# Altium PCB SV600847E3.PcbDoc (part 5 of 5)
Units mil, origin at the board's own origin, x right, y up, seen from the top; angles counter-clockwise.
Board outline 5404 x 2680 mil, 10 copper layers (Top Layer L1, Gnd-Plane - L2, Signals - L3, Gnd-Plane - L4, Pwr Plane - L5, Signals - L6, Gnd-Plane - L7, Signals - L8, Gnd-Plane - L9, Bottom Layer - L10), stack 57.8 mil thick; 517 components, 320 nets, 1784 pads, 1289 vias.
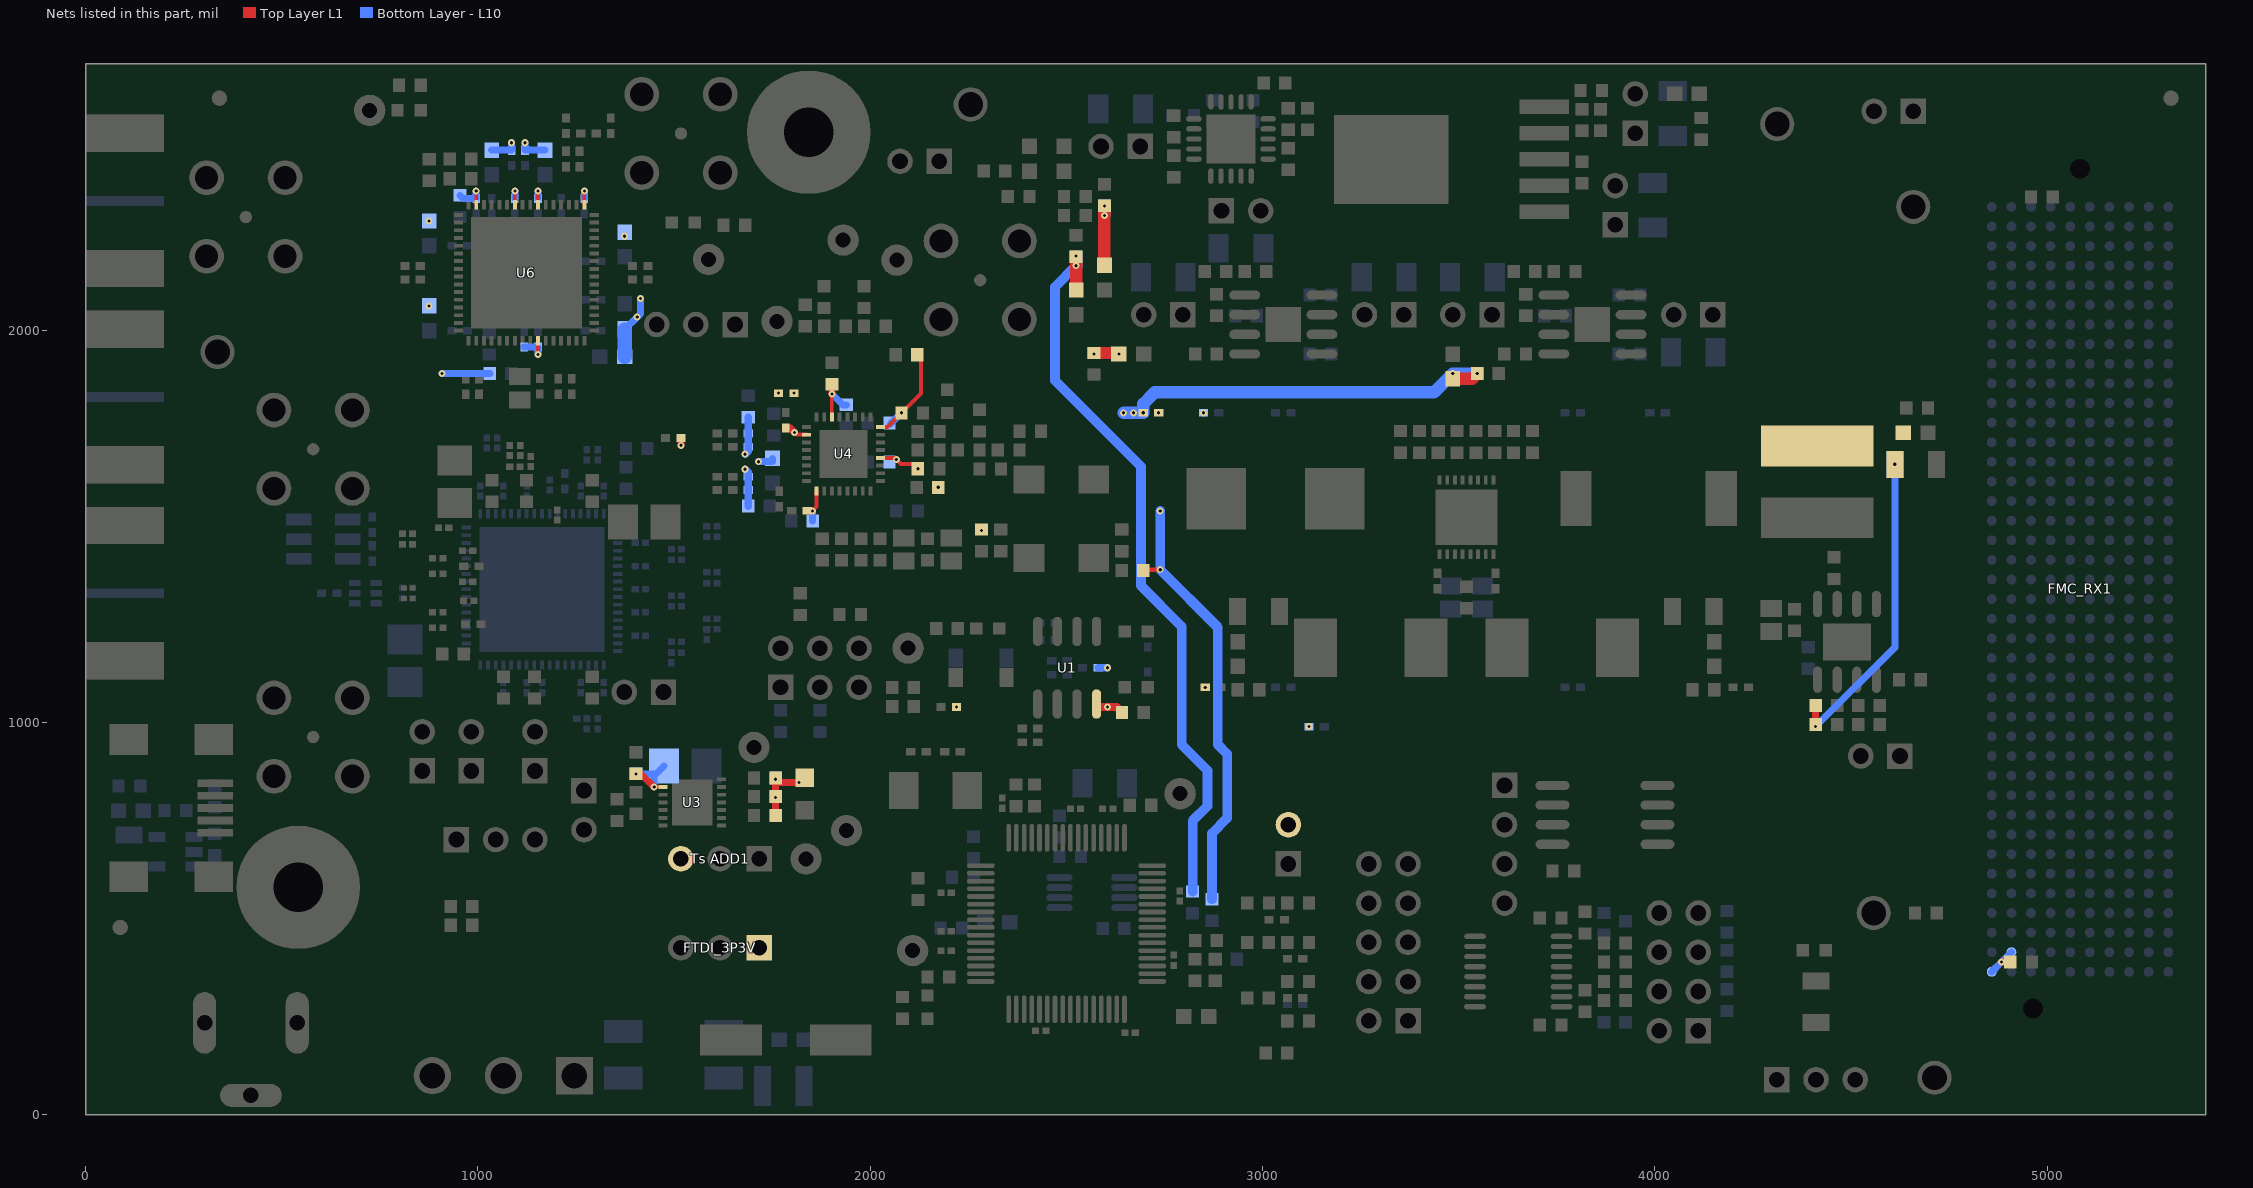
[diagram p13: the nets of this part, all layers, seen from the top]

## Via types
v1: diameter 18, hole 8, Top Layer L1 to Bottom Layer - L10, tented both sides, 1069 vias
v2: diameter 19.68, hole 7.87, Top Layer L1 to Bottom Layer - L10, 95 vias
v3: diameter 18, hole 8, Top Layer L1 to Bottom Layer - L10, tented bottom, 56 vias
v4: diameter 18, hole 8, Top Layer L1 to Bottom Layer - L10, tented top, 54 vias
v5: diameter 25.98, hole 12.99, Top Layer L1 to Bottom Layer - L10, tented top, 8 vias
v6: diameter 19.68, hole 7.87, Top Layer L1 to Bottom Layer - L10, tented top, 5 vias
v7: diameter 126, hole 106, Top Layer L1 to Bottom Layer - L10, tented top, 2 vias

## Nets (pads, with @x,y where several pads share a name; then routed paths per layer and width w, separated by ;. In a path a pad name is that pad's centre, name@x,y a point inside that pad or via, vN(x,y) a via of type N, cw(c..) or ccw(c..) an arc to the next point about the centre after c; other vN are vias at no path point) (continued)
VIO_3P3V: "Ts ADD1.3" C24.1 C25.1 C27.1 C115.1 C125.1 C153.1 C163.1 C215.1 C216.1 C217.1 C218.1 C219.2 C220.1 C224.2 FTDI_3P3V.1 J3.2 L9.2 R1.2 R14.2 R15.2 R16.2 R31.2 R32.2 TEMP.1 U1.8 U3.2 | length 670
  Top Layer L1 w9: v1(1449.28,836.13) U3.2@1471.47,836.13
  Top Layer L1 w18: v1(1403.28,869.44) 1415.96,869.44 v1(1449.28,836.13) ; v1(1517.68,1707.16) C215.1@1517.68,1726 ; R16.2@1758.84,763.41 v1(1758.84,809.41) 1758.84,847.47 v1(1818.28,847.47)
  Top Layer L1 w19.5: U1.8@2577,1040 2627.93,1040 C125.1@2641.93,1026
  Top Layer L1 w30: C153.1@2570,1942.56 2631.45,1942.56 v1(2634.01,1940)
  Bottom Layer - L10 w18: v1(1403.28,869.44) 1454.17,869.44 C27.1@1474.14,889.42 ; v1(1449.28,836.13) C27.1@1449.3,869.44 ; v1(1758.84,809.41) v1(1758.84,855.81) ; v1(2570,1940) v1(2634.01,1940) ; R1.2@2580.69,1140 v1(2604.5,1140)
  Bottom Layer - L10 w19.5: v1(2604.5,1040) 2627.93,1040 C115.1@2641.93,1026
  other v1: 3118.32,990 2219.68,1040 2854.16,1090 2735.24,1790 2849.31,1790 1766.32,1840
VIO_3P3V_LMK_CLK: C116.1 C171.1 L2.1 L4.1 L13.2 L19.1 L21.1 L22.1 R47.2 R131.1 | length 2191.3
  Top Layer L1 w31.5: L13.2@2525,2102.99 C116.1@2525,2187.44
  Bottom Layer - L10 w18: v1(908,1890) R47.2@1030.23,1890 ; L4.1@1373.92,2001.92 v1(1406,2034) 1414,2042 v1(1414,2081)
  Bottom Layer - L10 w25: v1(2525,2165) 2471,2111 2471,1872 2690,1653 2690,1349 2794,1245 2794,944 2860,878 2860,788 2822,750 R131.1@2822,569.71
  Bottom Layer - L10 w31.5: v1@2525,2162.44 C171.1@2525,2187.44
  Bottom Layer - L10 w37.5: L2.1@1373.92,1932.5 L4.1@1373.92,2001.92
  other v1: 875.5,2062.35 2525,2190 1373.92,2240 875.5,2278.89
VIO_3P3V_LMK_PLL: C102.1 C104.1 C107.1 C108.1 C109.1 C164.1 C165.1 C206.1 C207.1 C208.1 C209.1 L3.1 L5.1 L10.2 U6.10 U6.33 U6.39 U6.42 U6.47 | length 666.3
  Top Layer L1 w9: U6.47@995.61,2320.23 v1(995.61,2355.31) ; U6.42@1094.03,2320.23 v1(1094.03,2355.31) ; v1(1153.09,1938.69) U6.10@1153.09,1973.77 ; U6.39@1153.09,2320.23 v1(1153.09,2355.31) ; U6.33@1271.2,2320.23 v1(1271.2,2355.31)
  Top Layer L1 w31.5: L10.2@2597,2165.99 v1(2597,2317.5)
  Bottom Layer - L10 w18: C108.1@953.92,2344.32 961.79,2336.44 C209.1@995.61,2336.45 v1(995.61,2355.31) ; L5.1@1034.98,2459.5 C107.1@1085.92,2459.5 v1(1085.92,2478.37) ; C208.1@1094.03,2336.45 v1(1094.03,2355.31) ; C109.1@1117.72,1957.55 C102.1@1153.09,1957.55 v1(1153.09,1938.69) ; v1(1119.92,2478.37) C104.1@1119.92,2459.5 L3.1@1170.95,2459.5 ; C207.1@1153.09,2336.45 v1(1153.09,2355.31) ; C206.1@1271.2,2336.45 v1(1271.2,2355.31)
  Bottom Layer - L10 w31.5: v1(2597,2292.5) v1(2597,2317.5)
VIO_3P3V_LMX: C75.2 C76.2 C77.2 C78.2 C88.1 C89.1 C91.1 C94.1 C95.2 C98.2 C99.2 C144.1 C152.1 C216.2 C217.2 L1.1 L6.2 R24.1 R35.2 R36.1 R37.2 R38.1 R46.2 R117.2 R130.1 R133.2 U4.6 U4.10 U4.17 U4.28 U4.32 | length 3054.9
  Top Layer L1 w9: U4.6@1902.35,1779.45 v1(1902.35,1838)
  Top Layer L1 w10: v1(1806.92,1740) 1812.75,1734.17 U4.10@1837.39,1734.17 ; v1(1852.43,1540) 1862.98,1550.55 U4.17@1862.98,1590.47 ; U4.28@2026.36,1675.11 2062.5,1675.11 v1(2066.5,1671.11) 2078.62,1659 2109.99,1659 v1(2121.58,1647.41) ; U4.32@2026.36,1753.85 2043.85,1753.85 C77.2@2079.58,1789.58 2129,1839.01 2129,1928.87 R117.2@2119.87,1938
  Top Layer L1 w12.5: R133.2@2696.32,1390 v1(2739.2,1390)
  Top Layer L1 w18: C75.2@1839.62,1540 v1(1852.43,1540) ; v1(1902.35,1838) C89.1@1902.35,1862.75
  Top Layer L1 w19: C95.2@1784.89,1751.11 1795.81,1751.11 v1(1806.92,1740)
  Top Layer L1 w31.5: L6.2@3485,1876.5 3533.94,1876.5 v1(3547.44,1890)
  Bottom Layer - L10 w18: v1(1715,1665.27) 1751,1665.27 L1.1@1751,1674 ; C94.1@1852.43,1514.27 v1(1852.43,1540) ; v1(1902.35,1838) 1930.25,1810.1 C88.1@1938.95,1810.1 ; C78.2@2051.53,1761.95 v1(2079.58,1790)
  Bottom Layer - L10 w19: v1(1681,1646.11) 1688.96,1638.15 R36.1@1688.96,1593.27 C98.2@1688.96,1552.1 ; v1(1681,1684.43) 1688.96,1692.39 R37.2@1688.96,1737.27 C99.2@1688.96,1778.44
  Bottom Layer - L10 w25: v1(2739.2,1540) v1(2739.2,1390) 2886,1243.2 2886,944 2910,920 2910,757 2871,718 R130.1@2871,550.02
  Bottom Layer - L10 w31.5: v1(2645.87,1790) v1(2695.87,1790) 2695.87,1812.87 2725,1842 3437,1842 v1(3485,1890) v1(3547.44,1890)
  other v1: 2283.8,1490 2173.35,1600.02 2670.87,1790 1805.69,1840
VIO_3P6V: C154.2 C156.2 C157.2 L7.1 L8.2 R72.1 | length 801.4
  Top Layer L1 w18: R72.1@4409.88,995 C154.2@4409.88,1044
  Bottom Layer - L10 w18: v1(4409.88,990) 4611.85,1191.97 v1(4611.85,1658.75)
VIO_B_M2C_RX: FMC_RX1.J39 FMC_RX1.K40 RR7.2 | length 93.2
  Top Layer L1 w18: v1(4884,390) RR7.2@4906.44,390
  Bottom Layer - L10 w18: FMC_RX1.K40@4859,365 v1(4884,390) FMC_RX1.J39@4909,415
pads on no net: 5VDC.3 "SH-Ts ADD1_1_2.0" FID1.1 FID2.1 FID3.1 FMC_RX1.401 FMC_RX1.402 FMC_RX1.A22 FMC_RX1.A23 FMC_RX1.A26 FMC_RX1.A27 FMC_RX1.A30 FMC_RX1.A31 FMC_RX1.A34 FMC_RX1.A35 FMC_RX1.A38 FMC_RX1.A39 FMC_RX1.B1 FMC_RX1.B4 FMC_RX1.B5 FMC_RX1.B8 FMC_RX1.B9 FMC_RX1.B20 FMC_RX1.B21 FMC_RX1.B24 FMC_RX1.B25 FMC_RX1.B28 FMC_RX1.B29 FMC_RX1.B32 FMC_RX1.B33 FMC_RX1.B36 FMC_RX1.B37 FMC_RX1.B40 FMC_RX1.C2 FMC_RX1.C3 FMC_RX1.C10 FMC_RX1.C11 FMC_RX1.C14 FMC_RX1.C15 FMC_RX1.C18 FMC_RX1.C19 FMC_RX1.C22 FMC_RX1.C23 FMC_RX1.C26 FMC_RX1.C27 FMC_RX1.D8 FMC_RX1.D9 FMC_RX1.D11 FMC_RX1.D12 FMC_RX1.D14 FMC_RX1.D15 FMC_RX1.D17 FMC_RX1.D18 FMC_RX1.D20 FMC_RX1.D21 FMC_RX1.D23 FMC_RX1.D24 FMC_RX1.D27 FMC_RX1.D29 FMC_RX1.D33 FMC_RX1.D34 FMC_RX1.E2 FMC_RX1.E3 FMC_RX1.E6 FMC_RX1.E7 FMC_RX1.E9 FMC_RX1.E10 FMC_RX1.E15 FMC_RX1.E16 FMC_RX1.E18 FMC_RX1.E19 FMC_RX1.E21 FMC_RX1.E22 FMC_RX1.E24 FMC_RX1.E25 FMC_RX1.E27 FMC_RX1.E28 FMC_RX1.E30 FMC_RX1.E31 FMC_RX1.E33 FMC_RX1.E34 FMC_RX1.E37 FMC_RX1.F4 FMC_RX1.F5 FMC_RX1.F7 FMC_RX1.F8 FMC_RX1.F10 FMC_RX1.F11 FMC_RX1.F13 FMC_RX1.F14 FMC_RX1.F16 FMC_RX1.F17 FMC_RX1.F19 FMC_RX1.F20 FMC_RX1.F22 FMC_RX1.F23 FMC_RX1.F25 FMC_RX1.F26 FMC_RX1.F28 FMC_RX1.F29 FMC_RX1.F31 FMC_RX1.F32 FMC_RX1.F34 FMC_RX1.F35 FMC_RX1.F37 FMC_RX1.F38 FMC_RX1.G2 FMC_RX1.G3 FMC_RX1.G15 FMC_RX1.G16 FMC_RX1.G18 FMC_RX1.G19 FMC_RX1.G21 FMC_RX1.G22 FMC_RX1.G24 FMC_RX1.G25 FMC_RX1.G28 FMC_RX1.G31 FMC_RX1.H1 FMC_RX1.H4 FMC_RX1.H5 FMC_RX1.H7 FMC_RX1.H8 FMC_RX1.H10 FMC_RX1.H11 FMC_RX1.H13 FMC_RX1.H14 FMC_RX1.H16 FMC_RX1.H17 FMC_RX1.H19 FMC_RX1.H20 FMC_RX1.H25 FMC_RX1.H26 FMC_RX1.H28 FMC_RX1.H29 FMC_RX1.H32 FMC_RX1.H35 FMC_RX1.J2 FMC_RX1.J3 FMC_RX1.J6 FMC_RX1.J7 FMC_RX1.J9 FMC_RX1.J10 FMC_RX1.J12 FMC_RX1.J13 FMC_RX1.J18 FMC_RX1.J19 FMC_RX1.J21 FMC_RX1.J22 FMC_RX1.J24 FMC_RX1.J25 FMC_RX1.J27 FMC_RX1.J28 FMC_RX1.J30 FMC_RX1.J31 FMC_RX1.J33 FMC_RX1.J34 FMC_RX1.J36 FMC_RX1.J37 FMC_RX1.K1 FMC_RX1.K4 FMC_RX1.K5 FMC_RX1.K7 FMC_RX1.K8 FMC_RX1.K10 FMC_RX1.K11 FMC_RX1.K13 FMC_RX1.K14 FMC_RX1.K16 FMC_RX1.K17 FMC_RX1.K19 FMC_RX1.K20 FMC_RX1.K22 FMC_RX1.K23 FMC_RX1.K25 FMC_RX1.K26 FMC_RX1.K28 FMC_RX1.K29 FMC_RX1.K31 FMC_RX1.K32 FMC_RX1.K34 FMC_RX1.K35 FMC_RX1.K37 FMC_RX1.K38 H3.0 H4.0 H5.1 H6.1 S1.3 SH-1V2ADC_INT_1_2.0 SH-1V2ADC_LDO_1_2.0 SH-1V9ADC_1_2.0 SH-1V9INT_1_2.0 SH-5V_12V_1_2.0 SH-FTDI_3P3V_1_2.0 SH-LMK_INT_1_2.0 SH-LMK_LDO_1_2.0 SH-LMX_INT_1_2.0 SH-LMX_LDO_1_2.0 SH-RSV_1_2.0 U3.1 U3.3 U3.4 U5.2 U5.7 U8.2 U8.7 U10.2 U10.3 U10.4 U10.9 U10.13 U10.14 U10.17 U13.21 U13.22 U13.23 U13.24 U13.27 U13.29 U13.30 U13.32 U13.33 U13.34 U13.36 U13.45 U13.46 U13.48 U13.52 U13.53 U13.54 U13.55 U13.57 U13.58 U13.59 U13.60 U15.6 U15.7 U16.7 USB.4 uWIRE.1 uWIRE.3 uWIRE.5 uWIRE.7
copper on no net:
  other v7: 5005,100 5005,2580

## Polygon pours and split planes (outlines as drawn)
GND on Top Layer L1 "Top Layer L1-U9 GND" (solid, pour order 30): 3715,1819 2772,1819 2772,1111 2908,1111 2908,1177 2796,1177 2796,1660 2968,1660 2968,1111 3018,1111 3018,1032 3689,1032 3689,1105 3555,1105 3555,1307.54 3485,1307.54 3485,1105 3351,1105 3351,1266 3097,1266 3097,1660 3290,1660 3291,1363 3426,1363 3426,1453 3614,1453 3614,1363 3749,1363 3749,1660 3943,1660 3943,1266 3689,1266 3689,1032 4070,1032 4070,1110 4120,1110 4120,1660 4219,1660 4219,1176 4180,1176 4180,1110 4243,1110 4244,1782 4613,1782 4613,1819 3715,1819 3715,1663 3635,1663 3614,1642 3614,1596 3426,1596 3426,1642 3405,1663 3325,1663 3325,1769 3383,1769 3383,1728 3513,1728 3513,1769 3575,1769 3575,1728 3657,1728 3657,1769 3715,1769
GND on Top Layer L1 "Top Layer L1-U2-GND" (solid, pour order 39): 995,1182 995,1303 980,1303 980,1368 991,1368 991,1430 978,1430 978,1447 995,1447 995,1526 1322,1526 1322,1182
Net1V2ADC_INT_2 on Top Layer L1 "Top Layer L1-NetC172_1" (solid, pour order 43): 2994.68,2488 2994.68,2413 2964,2413 2964,2272 3034,2272 3034,2393 3083,2393 3083,2425 3033.68,2425 3033.68,2488
Net1V2ADC_LDO_1 on Top Layer L1 "Top Layer L1-NetC172_1" (solid, pour order 42): 2844.68,2495 2844.68,2413 2868.68,2413 2868.68,2374 2805.68,2374 2805.68,2430 2655.68,2430 2655.68,2508 2790.68,2508 2790.68,2495
VIO_1P9V on Top Layer L1 "Top Layer L1-VIO_1P9V" (solid, remove dead copper, pour order 44): 973,1301 953,1301 953,1297 947,1291 940,1291 934,1297 934,1363 940,1369 970,1369 970,1320 973,1320
GND on Top Layer L1 "Top Layer L1-GND" (solid, pour order 37): 1860.5,1331 1860.5,1430 2234.5,1430 2234.5,1331
5P0_12P0V_INT on Top Layer L1 "Top Layer L1-12P0_INT" (solid, pour order 33): 3555,1405 3485,1405 3485,1331 3555,1331 3555,1405
VIO_3P6V on Top Layer L1 "Top Layer L1-VIO_3P6V" (solid, pour order 52): 4634,1624 4634,1720 4653,1720 4653,1758 4270,1758 4270,1653 4575,1653 4575,1624
5P0_12P0V_INT on Top Layer L1 "Top Layer L1-U7-12V_int" (solid, pour order 51): 4427,1269 4427,1336 4269,1336 4269,1269
GND on Top Layer L1 "Top Layer L1-U7-SW_GND" (solid, pour order 50): 4427,1346 4427,1453 4269,1453 4269,1346
NetC168_1 on Top Layer L1 "Top Layer L1-NetC168_1" (solid, pour order 31): 3555,1643 3485,1643 3485,1704 3555,1704 3555,1643
NetC170_1 on Top Layer L1 "Top Layer L1-NetC170_1" (solid, pour order 54): 3476,1442 3465,1442 3465,1405 3461,1405 3461,1353 3281,1353 3281,1650 3107,1650 3107,1276 3361,1276 3361,1115 3476,1115
NetC169_2 on Top Layer L1 "Top Layer L1-NetC169_2" (solid, pour order 53): 3564,1442 3575,1442 3575,1405 3579,1405 3579,1353 3759,1353 3759,1650 3933,1650 3933,1276 3679,1276 3679,1115 3564,1115
VIO_1P4V on Top Layer L1 "Top Layer L1- VIO_1P4V" (solid, pour order 56): 2958,1650 2806,1650 2806,1186 2958,1186 2958,1650
VIO_2P25V on Top Layer L1 "Top Layer L1- VIO_1P4V" (solid, pour order 55): 4130,1650 4209,1650 4209,1186 4130,1186 4130,1650
GND on Top Layer L1 "Top Layer L1-U7-GND" (solid, pour order 49): 4740,1158 4740,1694 4696,1694 4696,1614 4575,1614 4575,1336 4553,1336 4553,1254 4269,1254 4269,1158 4661,1158 4661,1092 4694,1092 4694,1158
GND on Bottom Layer - L10 "Bottom Layer - L10-T2-GND" (solid, pour order 35): 403,1364 620,1364 620,1453 701,1453 701,1483 620,1483 620,1572 403,1572
5P0_12P0V_INT on Bottom Layer - L10 "Top Layer L10-12P0_INT" (solid, pour order 32): 3555,1405 3485,1405 3485,1327 3555,1327 3555,1405
GND on Bottom Layer - L10 "Bottom Layer - L10-U4-GND" (solid, pour order 40): 1871,1624 2010,1624 2010,1781 1978,1781 1978,1771 1871,1771
GND on Bottom Layer - L10 "Bottom Layer - L10-U6-GND" (solid, pour order 36): 961,1989 1012,1989 1012,1978 1046,1978 1046,1985 1286,1985 1286,2310 985,2310 985,2305 937,2305 937,2273 961,2273
GND on Bottom Layer - L10 "Bottom Layer - L10-U10-GND" (solid, pour order 34): 2856,2426 2992,2426 2992,2550 2856,2550 2841,2565 2809,2565 2809,2530 2856,2483
VIO_1P9V on Signals - L3 "Signals - L3-VIO_1P9V" (solid, pour order 38): 897,2660 4125,2660 4125,2094 2437,2094 2437,2285 2122,2285 2122,2094 1119,2094 1119,1592 1196,1592 1196,944 1095,944 1095,1046 769,1046 769,1142 897,1142
1P8V_USB on Signals - L3 "Signals - L3-1P8V_USB" (solid, pour order 48): 2215,387 2215,441 2304,441 2304,773 2368,773 2368,729 2641,729 2641,783 2680,783 2680,550 2368,550 2368,441 2808,441 2808,387
3P3V_FTDI on Signals - L3 "Signals - L3-3P3V_FTDI" (solid, pour order 46): 1584,572 2023,572 2023,970 2310,970 2310,888 2782.89,887.9 2909.9,760.89 2910,476 2818,476 2818,451 2378,451 2378,540 2690,540 2690,793 2631,793 2631,739 2378,739 2378,783 2294,783 2294,451 2205,451 2205,377 2818,377 2818,476 2910,476 2910,389 2825,304 2824.9,167.11 2737.89,80.1 2348.11,80.1 2225,203 2084.21,203 2023.1,264.11 2023.1,443 1650,443 1650,393 1584,393
3P3V_USB on Signals - L3 "Signals - L3-3P3V_USB" (solid, remove dead copper, pour order 45): 20.1,1029.9 400.9,1029.9 400.9,843.1 436,808 641,808 877,572 1550,572 1550,393 1485,393 1485,443 902,443 609,736 493,736 401,644 400.9,535.1 20.1,535.1
VIO_3P3V_LMK_CLK on Signals - L8 "Signals - L8-VIO_3P3V_LMK_CLK" (solid, pour order 47): 1521,2153 2756,2153 2756,2660 831,2660 831,1871 936,1871 936,2522 1311,2522 1311,2378 2656,2378 2656,2252 1310,2252 1310,2025 1423,2025 1423,2097 1400,2097 1400,2197 1477,2197
VIO_3P3V_LMK_PLL on Signals - L8 "Signals - L8-VIO_3P3V_LMK_PLL" (solid, pour order 41): 1108,1924 1168,1924 1168,1995 1203,2030 1286,2030 1286,2277 2631,2277 2631,2353 1286,2353 1286,2497 961,2497 961,1974 1108,1974
no net on Top Overlay "Top Overlay-No Net" (solid): 5254,139 5254,39 5354,39 5354,139 5254,139
no net on Top Overlay "Top Overlay-No Net" (solid): 5104,139 5104,39 5204,39 5204,139 5104,139
GND_OSC on Gnd-Plane - L2 (split plane): 2426.9,1980.1 2408.12,1980.1 2406.17,1979.71 2404.51,1978.6 2403.41,1976.95 2403.02,1975 2403.02,1675 2403.41,1673.05 2404.51,1671.4 2406.17,1670.29 2408.12,1669.9 2618.9,1669.9 2618.9,1518 2619.29,1516.05 2620.4,1514.4 2622.05,1513.29 2624,1512.9 2761.9,1512.9 2761.9,1370.1 2304.11,1370.1 2256.1,1418.11 2256.1,1720 2255.71,1721.95 2254.6,1723.6 2250.1,1728.11 2250.1,1975 2249.71,1976.95 2248.6,1978.6 2246.95,1979.71 2245,1980.1 2132.1,1980.1 2132.1,2274.9 2426.9,2274.9
GND2 on Gnd-Plane - L2 (split plane): 400.9,845 401.29,843.05 402.4,841.4 434.4,809.4 436.05,808.29 438,807.9 641.52,807.9 875.65,573.77 877.31,572.66 879.26,572.27 2018,572.27 2019.95,572.66 2021.6,573.77 2022.71,575.42 2023.1,577.37 2023.1,969.9 2309.9,969.9 2309.9,893 2310.29,891.05 2311.4,889.4 2313.05,888.29 2315,887.9 2782.89,887.9 2909.9,760.89 2909.9,389.11 2826.4,305.6 2825.29,303.95 2824.9,302 2824.9,167.11 2737.89,80.1 2348.11,80.1 2226.6,201.6 2224.95,202.71 2223,203.1 2084.11,203.1 2023.1,264.11 2023.1,438 2022.71,439.95 2021.6,441.6 2019.95,442.71 2018,443.1 902.11,443.1 610.6,734.6 608.95,735.71 607,736.1 495,736.1 493.05,735.71 491.4,734.6 402.4,645.6 401.29,643.95 400.9,642 400.9,535.1 20.1,535.1 20.1,1029.9 400.9,1029.9
GND on Gnd-Plane - L2 (split plane): 5383.9,20.1 20.1,20.1 20.1,524.9 406,524.9 407.95,525.29 409.6,526.4 410.71,528.05 411.1,530 411.1,639.89 497.11,725.9 604.89,725.9 896.39,434.4 898.05,433.29 900,432.9 2012.9,432.9 2012.9,262 2013.29,260.05 2014.4,258.4 2078.4,194.4 2080.05,193.29 2082,192.9 2220.89,192.9 2342.4,71.4 2344.05,70.29 2346,69.9 2740,69.9 2741.95,70.29 2743.6,71.4 2833.6,161.4 2834.71,163.05 2835.1,165 2835.1,299.89 2918.6,383.4 2919.71,385.05 2920.1,387 2920.1,763 2919.71,764.95 2918.6,766.6 2788.6,896.6 2786.95,897.71 2785,898.1 2320.1,898.1 2320.1,975 2319.71,976.95 2318.6,978.6 2316.95,979.71 2315,980.1 2018,980.1 2016.05,979.71 2014.4,978.6 2013.29,976.95 2012.9,975 2012.9,582.47 881.37,582.47 647.23,816.6 645.58,817.71 643.63,818.1 440.11,818.1 411.1,847.11 411.1,1035 410.71,1036.95 409.6,1038.6 407.95,1039.71 406,1040.1 20.1,1040.1 20.1,2659.9 5383.9,2659.9
GND on Gnd-Plane - L4 (split plane): 5383.9,20.1 20.1,20.1 20.1,2659.9 5383.9,2659.9
NetC158_1 on Pwr Plane - L5 (split plane): 5383.9,1995.1 4012.1,1995.1 4012.1,2419 4011.71,2420.95 4010.6,2422.6 4008.95,2423.71 4007,2424.1 3791,2424.1 3789.05,2423.71 3787.4,2422.6 3786.29,2420.95 3785.9,2419 3785.9,1995.1 3315.1,1995.1 3315.1,2659.9 5383.9,2659.9
VIO_2P25 on Pwr Plane - L5 (split plane): 4001.9,1184 4002.29,1182.05 4003.4,1180.4 4005.05,1179.29 4007,1178.9 4213.9,1178.9 4213.9,1045.1 3796.1,1045.1 3796.1,2413.9 4001.9,2413.9
VIO_1P4 on Pwr Plane - L5 (split plane): 3047.9,1045.1 2874.1,1045.1 2874.1,1990 2873.71,1991.95 2872.6,1993.6 2870.95,1994.71 2869,1995.1 2641.1,1995.1 2641.1,2659.9 3047.9,2659.9
5P0_12P0V_INT on Pwr Plane - L5 (split plane): 3304.9,1990 3305.29,1988.05 3306.4,1986.4 3308.05,1985.29 3310,1984.9 3785.9,1984.9 3785.9,1040 3786.29,1038.05 3787.4,1036.4 3789.05,1035.29 3791,1034.9 4219,1034.9 4220.95,1035.29 4222.6,1036.4 4223.71,1038.05 4224.1,1040 4224.1,1184 4223.71,1185.95 4222.6,1187.6 4220.95,1188.71 4219,1189.1 4012.1,1189.1 4012.1,1984.9 5383.9,1984.9 5383.9,670.1 5209,670.1 5207.05,669.71 5205.4,668.6 5204.29,666.95 5203.9,665 5203.9,570.1 4461,570.1 4459.05,569.71 4457.4,568.6 4456.29,566.95 4455.9,565 4455.9,20.1 4366.1,20.1 4366.1,190 4365.71,191.95 4364.6,193.6 4362.95,194.71 4361,195.1 3143.1,195.1 3143.1,1040 3142.71,1041.95 3141.6,1043.6 3139.95,1044.71 3138,1045.1 3058.1,1045.1 3058.1,2659.9 3304.9,2659.9
12P0V_RX on Pwr Plane - L5 (split plane): 5383.9,20.1 4466.1,20.1 4466.1,559.9 5209,559.9 5210.95,560.29 5212.6,561.4 5213.71,563.05 5214.1,565 5214.1,659.9 5383.9,659.9
VIO_1P2VD on Pwr Plane - L5 (split plane): 2630.9,1995.1 2536,1995.1 2534.05,1994.71 2532.4,1993.6 2531.29,1991.95 2530.9,1990 2530.9,1945.1 2117,1945.1 2115.05,1944.71 2113.4,1943.6 2089.89,1920.1 1435,1920.1 1433.05,1919.71 1431.4,1918.6 1401.4,1888.6 1400.29,1886.95 1399.9,1885 1399.9,1710 1400.29,1708.05 1401.4,1706.4 1434.9,1672.89 1434.9,1245 1435.29,1243.05 1436.4,1241.4 1438.05,1240.29 1440,1239.9 2003.9,1239.9 2003.9,1040.1 1200,1040.1 1198.05,1039.71 1196.4,1038.6 1195.29,1036.95 1194.9,1035 1194.9,657.1 1095.1,657.1 1095.1,1779.89 1094.71,1781.84 1093.6,1783.5 1030.1,1847.01 1030.1,1988.85 1117.15,2075.9 2450,2075.9 2451.95,2076.29 2453.6,2077.4 2454.71,2079.05 2455.1,2081 2455.1,2659.9 2630.9,2659.9
VIO_3P3V_LMX on Pwr Plane - L5 (split plane): 1916.9,1840 1917.29,1838.05 1918.4,1836.4 1920.05,1835.29 1922,1834.9 2710.45,1834.9 2710.45,1740 2710.84,1738.05 2711.95,1736.4 2713.6,1735.29 2715.55,1734.9 2753.45,1734.9 2753.45,1468.1 2207.11,1468.1 2158.6,1516.6 2156.95,1517.71 2155,1518.1 1720.1,1518.1 1720.1,1617 1719.71,1618.95 1718.6,1620.6 1716.95,1621.71 1715,1622.1 1671.1,1622.1 1671.1,1707.17 1786,1707.17 1787.95,1707.56 1789.6,1708.67 1790.71,1710.32 1791.1,1712.27 1791.1,1859.9 1916.9,1859.9
VIO_1P2VA on Pwr Plane - L5 (split plane): 2444.9,2086.1 1115.04,2086.1 1113.09,2085.71 1111.43,2084.6 1021.4,1994.57 1020.29,1992.91 1019.9,1990.96 1019.9,1844.89 1020.29,1842.94 1021.4,1841.29 1084.9,1777.78 1084.9,1040.1 20.1,1040.1 20.1,2659.9 2444.9,2659.9
NetC194_1 on Pwr Plane - L5 (split plane): 400.9,845 401.29,843.05 402.4,841.4 434.4,809.4 436.05,808.29 438,807.9 641.52,807.9 875.65,573.77 877.31,572.66 879.26,572.27 1662.18,572.27 1662.18,376 1662.57,374.05 1663.67,372.4 1665.33,371.29 1667.28,370.9 1767.28,370.9 1769.23,371.29 1770.88,372.4 1771.99,374.05 1772.37,376 1772.37,572.27 2018,572.27 2019.95,572.66 2021.6,573.77 2022.71,575.42 2023.1,577.37 2023.1,969.9 2309.9,969.9 2309.9,893 2310.29,891.05 2311.4,889.4 2313.05,888.29 2315,887.9 2782.89,887.9 2909.9,760.89 2909.9,190 2910.29,188.05 2911.4,186.4 2913.05,185.29 2915,184.9 4355.9,184.9 4355.9,20.1 20.1,20.1 20.1,1029.9 400.9,1029.9
VIO_3P3V on Pwr Plane - L5 (split plane): 2863.9,1040 2864.29,1038.05 2865.4,1036.4 2867.05,1035.29 2869,1034.9 3132.9,1034.9 3132.9,195.1 2920.1,195.1 2920.1,763 2919.71,764.95 2918.6,766.6 2788.6,896.6 2786.95,897.71 2785,898.1 2320.1,898.1 2320.1,975 2319.71,976.95 2318.6,978.6 2316.95,979.71 2315,980.1 2018,980.1 2016.05,979.71 2014.4,978.6 2013.29,976.95 2012.9,975 2012.9,582.47 1767.28,582.47 1765.33,582.08 1763.67,580.98 1762.57,579.32 1762.18,577.37 1762.18,381.1 1672.37,381.1 1672.37,577.37 1671.99,579.32 1670.88,580.98 1669.23,582.08 1667.28,582.47 1667.27,582.47 881.37,582.47 647.23,816.6 645.58,817.71 643.63,818.1 440.11,818.1 411.1,847.11 411.1,1029.9 1084.9,1029.9 1084.9,652 1085.29,650.05 1086.4,648.4 1088.05,647.29 1090,646.9 1200,646.9 1201.95,647.29 1203.6,648.4 1204.71,650.05 1205.1,652 1205.1,1029.9 2009,1029.9 2010.95,1030.29 2012.6,1031.4 2013.71,1033.05 2014.1,1035 2014.1,1245 2013.71,1246.95 2012.6,1248.6 2010.95,1249.71 2009,1250.1 1445.1,1250.1 1445.1,1675 1444.71,1676.95 1443.6,1678.6 1410.1,1712.11 1410.1,1882.89 1437.11,1909.9 2092,1909.9 2093.95,1910.29 2095.6,1911.4 2119.11,1934.9 2536,1934.9 2537.95,1935.29 2539.6,1936.4 2540.71,1938.05 2541.1,1940 2541.1,1984.9 2863.9,1984.9
GND on Gnd-Plane - L7 (split plane): 5383.9,20.1 20.1,20.1 20.1,2659.9 5383.9,2659.9
GND on Gnd-Plane - L9 (split plane): 5383.9,20.1 20.1,20.1 20.1,2659.9 5383.9,2659.9

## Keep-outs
Keep-Out Layer:
  text ".Layer_Name" at 577,-858.49 h60

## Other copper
Top Layer L1:
  text ".CopyrightYear" at 4374,2073 h60
  text "TI" at 4650,2073 h60
  text "©" at 4257,2069.48 h105
  text ".Layer_Name" at 577,-858.49 h60
Signals - L3:
  text ".Layer_Name" at 577,-858.49 h60
Signals - L6:
  text ".Layer_Name" at 577,-858.49 h60
Signals - L8:
  text ".Layer_Name" at 577,-858.49 h60
Bottom Layer - L10:
  text ".VersionControl_RevNumber" at 7392,2477.5 h60
  text "SVN:" at 7671,2477.5 h60
  text "MADE IN U.S." at 4740,733 h60
  text "UL94V-0" at 4631,590 h60
  text ".Layer_Name" at 577,-858.49 h60
Gnd-Plane - L9 (plane layer: these items are gaps in the copper):
  text ".Layer_Name" at 577,-858.49 h60
Gnd-Plane - L7 (plane layer: these items are gaps in the copper):
  text ".Layer_Name" at 577,-858.49 h60
Gnd-Plane - L4 (plane layer: these items are gaps in the copper):
  text ".Layer_Name" at 577,-858.49 h60
  text ".Layer_Name" at 577,-858.49 h60
Gnd-Plane - L2 (plane layer: these items are gaps in the copper):
  lines w10: 0,530 406,530 406,642 495,731 607,731 900,438 2018,438 2018,262 2082,198 2223,198 2346,75 2740,75 2830,165 2830,302 2915,387 2915,763 2785,893 2315,893 2315,975 2018,975 2018,577.37 879.26,577.37 643.63,813 438,813 406,845 406,1035 0,1035 ; 2432,1975 2408.12,1975 2408.12,1675 2624,1675 2624,1518 2767,1518 2767,1365 2302,1365 2251,1416 2251,1720 2245,1726 2245,1975 2127,1975 2127,2280 2432,2280 2432,1977
  text ".Layer_Name" at 577,-858.49 h60
Pwr Plane - L5 (plane layer: these items are gaps in the copper):
  lines w10: 0,1035 1090,1035 ; 406,1035 406,845 438,813 643.63,813 879.26,577.37 1667.28,577.37 1667.28,376 1767.28,376 1767.28,577.37 2018,577.37 2018,975 2315,975 2315,893 2785,893 2915,763 2915,190 4361,190 4361,0 ; 2450,2680 2450,2081 1115.04,2081 1025,1990.96 1025,1844.89 1090,1779.89 1090,652 1200,652 1200,1035 2009,1035 2009,1245 1440,1245 1440,1675 1405,1710 1405,1885 1435,1915 2092,1915 2117,1940 2536,1940 2536,1990 2869,1990 2869,1040 3053,1040 ; 2636,1990 2636,2680 ; 3053,2680 3053,1040 ; 3138,190 3138,1040 3053,1040 ; 3310,2680 3310,1990 3791,1990 ; 4007,1990 5404,1990 ; 4461,0 4461,565 5209,565 5209,665 5404,665 ; 1666,1617 1715,1617 1715,1513 2155,1513 2205,1463 2758.55,1463 2758.55,1740 2715.55,1740 2715.55,1840 1922,1840 1922,1865 1786,1865 1786,1712.27 1666,1712.27 1666,1617 ; 3791,1040 3791,2419 4007,2419 4007,1184 4219,1184 4219,1040 3791,1040
  text ".Layer_Name" at 577,-858.49 h60

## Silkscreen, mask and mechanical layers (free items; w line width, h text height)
Top Overlay:
  text "LM15851" at 5184,190 h60 r90
  text "ADC12J4000" at 5334,190 h60 r90
  text ".Layer_Name" at 577,-858.49 h60
Bottom Overlay:
  rectangle: 3723,1423 4023,1523
  text ".PCB_Rev" at 4223,1433 h60
  text ".PRJ_Number" at 4734,1433 h60
  text "-" at 4088,1422.5 h60
  text ".Layer_Name" at 577,-858.49 h60
Top Paste:
  text ".Layer_Name" at 577,-858.49 h60
Bottom Paste:
  text ".Layer_Name" at 577,-858.49 h60
Top Solder:
  text ".Layer_Name" at 577,-858.49 h60
  text ".Layer_Name" at 577,-858.49 h60
Bottom Solder:
  text ".Layer_Name" at 577,-858.49 h60
Drill Guide:
  text ".Layer_Name" at 577,-858.49 h60
M1 Board Outline:
  the board outline again, w10
  text ".Layer_Name" at 577,-858.49 h60
M2 Board Dimensions:
  rectangle: 124.5,-410.5 499.5,-285.5
  rectangle: -0.5,-285.5 124.5,-160.5
  lines w7: -0.5,-285.5 999.5,-285.5 ; 124.5,-410.5 124.5,-160.5 ; 249.5,-410.5 249.5,-160.5 ; 499.5,-410.5 499.5,-160.5 ; 749.5,-410.5 749.5,-160.5 ; -0.5,-410.5 -0.5,-160.5 999.5,-160.5 999.5,-410.5 -0.5,-410.5
  lines w10: -0.5,-475.5 -0.5,-455.5 ; 59.5,-485.5 -0.5,-465.5 ; 59.5,-445.5 -0.5,-465.5 ; 223.58,-465.5 -0.5,-465.5 ; 775.42,-465.5 999.5,-465.5 ; 939.5,-485.5 999.5,-465.5 ; 939.5,-445.5 999.5,-465.5 ; 999.5,-475.5 999.5,-455.5
  text "1000 (mil)" at 233.58,-501.49 h60
  text ".Layer_Name" at 577,-858.49 h60
M3 3D STEP Top:
  text ".Layer_Name" at 577,-858.49 h60
M4 3D STEP Bottom:
  text ".Layer_Name" at 577,-858.49 h60
M5 Assembly Top:
  lines w7: 5593,110.5 6718,110.5 ; 5593,233 6715.5,233 ; 5908,-9.5 5908,353 ; 6293,-9.5 5593,-9.5 ; 6293,353 5593,353 ; 5593,-9.5 5593,353 ; 5593,-9.5 6718,-9.5 6718,353 5593,353
  lines w10: -292,-930.17 6308,-930.17 ; -292,-726.83 6310,-726.83 ; -292,-523.5 -292,-1133.5 3713,-1133.5 6310,-1133.5 6310,-523.5 -291.5,-523.5 -291.5,-1133.5 1284,-1133.5 ; 2173,-1133.5 2173,-523.5 ; 3440,-726.83 3440,-523.5 ; 4280,-726.83 4280,-523.5 ; 4902,-1140 4902,-937.17
  text "TABLE 1" at 5980.5,388 h40
  text "Variant" at 5618,278 h40
  text "Label text" at 6053,278 h40
  text "001" at 5685.5,158 h40
  text "LM15851EVM" at 5963,155.5 h40
  text "002" at 5685.5,33 h40
  text "ADC12J4000EVM" at 5958,30.5 h40
  text "COMPONENTS MARKED 'DNP' SHOULD NOT BE POPULATED, AND MAY NOT BE IN BILL OF MATERIALS" at 1153.5,-318.5 h60
  text "ASSEMBLY VARIANT:" at 1153,-434 h60
  text ".VariantName" at 2189,-434 h60
  text "PCB VIEWED FROM TOP SIDE" at -228.5,-655.67 h60
  text "BOARD #:" at 2248,-655.67 h60
  text ".PRJ_Number" at 2793.5,-655.67 h60
  text "REV:" at 3638,-655.67 h60
  text ".PCB_Rev" at 3929.5,-655.67 h60
  text "SVN REV:" at 4476,-655.67 h60
  text ".VersionControl_RevNumber" at 4982,-655.67 h60
  text "IGNORE ->" at -228.5,-858.49 h60
  text "PLOT NAME =" at -228.5,-1064.34 h60
  text ".plot_File_Name" at 577,-1064.34 h60
  text "GENERATED    :" at 2250,-1064.34 h60
  text ".Print_Date" at 3119.5,-1064.34 h60
  text ".Print_Time" at 3848.5,-1064.34 h60
  text "TEXAS INSTRUMENTS" at 5113,-1064.34 h60
M6 Assembly Bottom:
  lines w10: -292.5,-727.33 6309.5,-727.33 ; -290.5,-930.67 6309.5,-930.67 ; 1115.5,-1140.5 1115.5,-937.67 ; 1737.5,-727.33 1737.5,-524 ; 2577.5,-727.33 2577.5,-524 ; 3844.5,-1134 3844.5,-524 ; 4733.5,-1134 6309,-1134 6309,-524 -292.5,-524 -292.5,-1134 2304.5,-1134 6309.5,-1134 6309.5,-524
  text "COMPONENTS MARKED 'DNP' SHOULD NOT BE POPULATED, AND MAY NOT BE IN BILL OF MATERIALS" at 6102,-318 h60
  text ".VariantName" at 5058,-434 h60
  text "ASSEMBLY VARIANT:" at 6097,-434 h60
  text ".VersionControl_RevNumber" at 1035.5,-656.17 h60
  text "SVN REV:" at 1541.5,-656.17 h60
  text ".PCB_Rev" at 2088,-656.17 h60
  text "REV:" at 2379.5,-656.17 h60
  text ".PRJ_Number" at 3224,-656.17 h60
  text "BOARD #:" at 3769.5,-656.17 h60
  text "PCB VIEWED FROM BOTTOM SIDE" at 6246,-656.17 h60
  text "IGNORE ->" at 2547.85,-858.49 h60
  text "TEXAS INSTRUMENTS" at 904.5,-1064.84 h60
  text ".Print_Time" at 2169,-1064.84 h60
  text ".Print_Date" at 2898,-1064.84 h60
  text "GENERATED    :" at 3767.5,-1064.84 h60
  text ".plot_File_Name" at 5440.5,-1064.84 h60
  text "PLOT NAME =" at 6246,-1064.84 h60
M9 Title Sheet:
  drawing of 57 lines, arcs and shapes, not listed
  text "1" at 739.84,8036.5 h70
  text "2" at 3235.5,8036.5 h70
  text "3" at 5724.84,8036.5 h70
  text "4" at 8231.51,8036.5 h70
  text "5" at 10730.5,8036.5 h70
  text "6" at 13235.5,8036.5 h70
  text "A" at -416.5,6893.5 h70
  text "A" at 14383.5,6893.5 h70
  text "B" at -416.5,4513.5 h70
  text "B" at 14383.5,4513.5 h70
  text "C" at -416.5,2138.5 h70
  text "C" at 14383.5,2138.5 h70
  text "PROJECT TITLE:" at 11343.5,277.5 h45
  text ".PRJ_Title" at 11393.5,144.17 h70
  text "DESIGNED FOR:" at 11343.5,-23.5 h45
  text ".PRJ_Customer" at 11393.5,-163.5 h70
  text "D" at -416.5,-231.5 h70
  text "D" at 14383.5,-231.5 h70
  text "FILE NAME:" at 11343.5,-323.5 h45
  text ".PCB_File_Name_No_Path" at 11393.5,-443.5 h70
  text "Texas Instruments (TI) and/or its licensors do not warrant the accuracy or completeness of this specification" at 6374,-605.34 h45
  text "ENGINEER:" at 11343.5,-613.5 h45
  text "LAYOUT BY:" at 12848.5,-613.5 h45
  text "or any information contained therein. TI and/or its licensors do not warrant that this design will meet" at 6329.01,-718 h45
  text ".PRJ_Engineer" at 11393.5,-768.49 h70
  text ".PCB_Layout" at 12899,-768.49 h70
  text "the specifications, will be suitable for your application or fit for any particular purpose, or will operate in" at 6329.01,-830.67 h45
  text ".Layer_Name" at 577,-858.49 h60
  text "ALTIUM DESIGNER VERSION:" at 12848.5,-923.5 h45
  text "an implementation. TI and/or its licensors do not warrant that the design is production worthy. You should" at 6329.01,-943.33 h45
  text "completely validate and test your design implementation to confirm the system functionality for your application." at 6374,-1056 h45
  text ".print_Scale" at 11393.5,-1056.83 h70
  text ".Application_BuildNumber" at 12899,-1056.83 h70
  text "1" at 739.84,-1263.5 h70
  text "2" at 3235.5,-1263.5 h70
  text "3" at 5724.84,-1263.5 h70
  text "4" at 8231.51,-1263.5 h70
  text "5" at 10730.5,-1263.5 h70
  text "6" at 13235.5,-1263.5 h70
M10 Fab Notes:
  drawing of 207 lines, arcs and shapes, not listed
  text "DESIGN INFORMATION" at 12381.02,6810 h60
  text "(REFER ALSO ARRAY/PANEL PROFILING INFORMATION)" at 12019.46,6648.29 h60
  text "BOARD SIZE" at 11333.46,6644 h60
  text "X" at 12301.46,6516.18 h60
  text "Number of Layers :" at 11736.46,6319 h60
  text "10" at 12831.27,6309 h60
  text "MIN. TRACK WIDTH:" at 11736.46,6180 h60
  text "4" at 12832.7,6180 h60
  text "MIL" at 12987.46,6180 h60
  text "MIN. CLEARANCE:" at 11736.46,6048 h60
  text "4" at 12832.7,6048 h60
  text "MIL" at 12987.46,6048 h60
  text "MIN. VIA PAD SIZE:" at 11736.46,5916 h60
  text "18" at 12802.71,5916 h60
  text "MIL" at 12987.46,5916 h60
  text "0.05mm (2MIL)" at 12431.46,5774.29 h60
  text "MINIMUM ANNULAR RING" at 11407.23,5770 h60
  text "EXTERNAL" at 13139.46,5770 h60
  text "PER" at 11607.23,5652 h60
  text "IPC-D-275 CLASS 2 LEVEL C" at 11827.23,5652 h60
  text "MIL, HOLES" at 13315.46,5539.71 h60
  text "+/-" at 12923,5539 h60
  text "+/-" at 13777,5539 h60
  text "REGISTRATION TOLERANCES:" at 11407.23,5534 h60
  text "METAL" at 12607,5534 h60
  text "5" at 13183.2,5534 h60
  text "3" at 14016.2,5534 h60
  text "MIL" at 14132.46,5534 h60
  text "MATERIAL:" at 11332.46,5324.54 h60
  text "FR-4 High Tg" at 12318.9,5184.21 h60
  text "FR-4" at 11793.46,5175.64 h60
  text "X" at 13054.46,5176 h60
  text "OTHER SEE LAYER STACK UP" at 13241.46,5175.64 h50
  text "62 MIL (1.6mm) +/-10%" at 12073.56,5012.92 h60
  text "THICKNESS:" at 11407.23,5008.64 h60
  text "X" at 11945.4,5008.64 h60
  text "OTHER" at 13358.46,5008.64 h60
  text "TOLERANCE:" at 11407.23,4850.64 h60
  text "X" at 12246.53,4850.64 h60
  text "ANSI IPC-6012 TYPE 3 CLASS 2" at 12433.48,4850.64 h60
  text "OTHER +/-" at 12433.46,4694.64 h60
  text "BOW & TWIST:" at 11407.23,4537.64 h60
  text "X" at 12246.53,4537.64 h60
  text "ANSI IPC-6012 TYPE 3 CLASS 2" at 12433.48,4537.64 h60
  text "OTHER +/-" at 12433.46,4379.13 h60
  text "COPPER THICKNESS (FINISHED):" at 11332.46,4243.64 h60
  text "SEE 001svengprerelstackup18.pdf FOR CORRECT IMPEDANCE INFORMATION" at 5000,4175 h100
  text "0.7MIL (0.5oz)" at 12212.46,4090.92 h60
  text "1.4MIL (1oz)" at 12979.46,4090.92 h60
  text "2.8MIL (2oz)" at 13706.46,4090.92 h60
  text "OUTER:" at 11689.46,4086.64 h60
  text "X" at 12084,4086 h60
  text "0.7MIL (0.5oz)" at 12212.46,3933.92 h60
  text "2.8MIL (2oz)" at 12979.46,3933.92 h60
  text "N/A" at 13706,3934.29 h60
  text "INNER SIGNAL:" at 11400.38,3929.64 h60
  text "X" at 12085.42,3929.64 h60
  text "X" at 12852.42,3929.64 h60
  text "Single ended tracks 50 ohms Top & Bottom Layers equal 8.0mil width." at 5000,3900 h100
  text "DRILLING:" at 11332.46,3790.64 h60
  text "REFERENCE:" at 11407.23,3673.64 h60
  text "X" at 12055.46,3673.64 h60
  text "AS SHOWN" at 12242.46,3673.64 h60
  text "X" at 12956.46,3673.64 h60
  text "NC_DRILL FILES" at 13093.46,3673.64 h60
  text "Differential tracks 100 ohms Top & Bottom Layers equal 8.0mil width & 8.0mil spacing." at 5000,3625 h100
  text "PTH MIN COPPER THICKNESS:" at 11407.23,3515.64 h60
  text "X" at 12757.46,3515.64 h60
  text "1MIL" at 12894.46,3515.64 h60
  text "OTHER" at 13391.46,3515.64 h60
  text "BOARD FINISH:" at 11332.46,3356.64 h60
  text "Differential tracks 100 ohms Inner Layers equal 4.0mil width & 4.0mil spacing." at 5000,3350 h100
  text "SILKSCREEN:" at 11487.68,3238.64 h60
  text "X" at 12436.46,3238.64 h60
  text "TOP" at 12562.46,3238.64 h60
  text "X" at 12946.46,3238.64 h60
  text "BOTTOM" at 13073.46,3238.64 h60
  text "Back Drill high speed lines 8.001 mil vias from Layer 1 to Layer 7, leaving the via" at 5000,3075 h100
  text "SILKSCREEN COLOR:" at 11487.68,3071.64 h60
  text "X" at 12435.42,3071.64 h60
  text "WHITE" at 12562.46,3071.64 h60
  text "OTHER" at 13073.46,3071.64 h60
  text "SOLDER RESIST COLOR:" at 11487.68,2901.64 h60
  text "connecting layer 8 to layer 10." at 5000,2800 h100
  text "X" at 12055.42,2742.44 h60
  text "GREEN" at 12182.46,2742.44 h60
  text "BLUE" at 12773.46,2742.44 h60
  text "OTHER" at 13311.46,2742.44 h60
  text "IMMERSION GOLD (ENIG)" at 12393.46,2553.92 h60
  text "SURFACE FINISH:" at 11332.46,2549.64 h60
  text "X" at 12206.51,2549.64 h60
  text "IMM. TIN/SILVER OR EQUIV" at 11662,2392.64 h60
  text "OTHER" at 13093.46,2392.64 h60
  text "ARRAY/PANEL:" at 11332.46,2213.64 h60
  text "CUT AND TRIM PER MECH LAYER 1" at 12393.46,2209.35 h60
  text "N.C. ROUTE" at 12393.46,2057.64 h60
  text "X" at 13072.46,2057.64 h60
  text "V. SCORE" at 13259.46,2057.64 h60
  text "CERTIFICATION:" at 11332.46,1920.64 h60
  text "MATERIALS AND WORKMANSHIP FOR ALL PCBS" at 12057.46,1920.64 h60
  text "TO MEET OR EXCEED THE REQUIREMENTS OF:" at 12057.46,1822.64 h60
  text "X" at 11683.96,1686.13 h60
  text "ANSI IPC-A-600F CLASS ->" at 11822.96,1686.13 h60
  text "X" at 13462.02,1686.13 h60
  text "2" at 13580.96,1686.14 h60
  text "1" at 13265.96,1684.64 h60
  text "3" at 13934.96,1684.64 h60
  text "X" at 11686.02,1526.64 h60
  text "UL 94V-0" at 11822.96,1526.64 h60
  text "X" at 12498.02,1526.64 h60
  text "RoHS" at 12634.96,1526.64 h60
  text "OTHER" at 13279.36,1526.64 h60
  text "PER ORDER" at 13676.42,1526.64 h60
  text "ADDITIONAL REQUIREMENTS:" at 11332.46,1385.64 h60
  text "MICROSECTION:" at 11407.23,1270.64 h60
  text "YES" at 12312.96,1270.64 h60
  text "REQUIRED" at 13174.46,1114.49 h60
  text "BARE BOARD ELEC. TEST:" at 11407.23,1111.64 h60
  text "NONE" at 12712.96,1111.64 h60
  text "X" at 13047.46,1111.64 h60
  text "PER ORDER" at 13766.46,1111.64 h60
  text "MANUFACTURER'S ID/LOGO:" at 11407.23,954.64 h60
  text "RAIL" at 12872.96,950.35 h60
  text "X" at 13247.46,950.35 h60
  text "METAL" at 13364.77,950.35 h60
  text "SILK" at 13876.46,950.35 h60
  text ".Layer_Name" at 577,-858.49 h60
M11 Gerber Information:
  lines w10: -292,-930.17 6308,-930.17 ; -292,-726.83 6310,-726.83 ; -292,-523.5 -292,-1133.5 3713,-1133.5 6310,-1133.5 6310,-523.5 -291.5,-523.5 -291.5,-1133.5 1284,-1133.5 ; 2173,-1133.5 2173,-523.5 ; 3440,-726.83 3440,-523.5 ; 4280,-726.83 4280,-523.5 ; 4902,-1140 4902,-937.17
  text "ALL ARTWORK VIEWED FROM TOP SIDE" at -228.5,-655.67 h60
  text "BOARD #:" at 2248,-655.67 h60
  text ".PRJ_Number" at 2793.5,-655.67 h60
  text "REV:" at 3638,-655.67 h60
  text ".PCB_Rev" at 3929.5,-655.67 h60
  text "SVN REV:" at 4476,-655.67 h60
  text ".VersionControl_RevNumber" at 4982,-655.67 h60
  text "LAYER NAME =" at -228.5,-858.49 h60
  text "PLOT NAME =" at -228.5,-1064.34 h60
  text ".plot_File_Name" at 577,-1064.34 h60
  text "GENERATED    :" at 2250,-1064.34 h60
  text ".Print_Date" at 3119.5,-1064.34 h60
  text ".Print_Time" at 3848.5,-1064.34 h60
  text "TEXAS INSTRUMENTS" at 5113,-1064.34 h60
M12 Stackup:
  lines w11: 4912,4388 4125,6075 4912,7762
  lines w12: 5018.02,7259.85 11193.98,7259.85 ; 5018.02,7472.75 11193.98,7472.75 ; 4955,4449 ccw(c5024,4449) 5024,4380 11188,4380 ccw(c11188,4449) 11257,4449 11257,7692 ccw(c11188,7692) 11188,7761 5024,7761 ccw(c5024,7692) 4955,7692 4955,4449
  text "Layer Stack Up Detail for: SV600847A1.PcbDoc" at 5018.02,7534.88 h110
  text "Layer" at 5018.02,7393.25 h49
  text "Gerber" at 6358.46,7393.25 h49
  text "Copper" at 7016.09,7393.25 h49
  text "Dielectric" at 7753.73,7393.25 h49
  text "Dielectric" at 8525.66,7393.25 h49
  text "Dielectric" at 9509.72,7393.25 h49
  text "Dielectric" at 10281.65,7393.25 h49
  text "Name" at 5018.02,7295.25 h49
  text "Document" at 6358.46,7295.25 h49
  text "Thickness" at 7016.09,7295.25 h49
  text "Height" at 7753.73,7295.25 h49
  text "Material" at 8525.66,7295.25 h49
  text "Constant" at 9509.72,7295.25 h49
  text "Type" at 10281.65,7295.25 h49
  text "Top Solder Mask" at 5018.02,7142.44 h69
  text "(.GTS)" at 6358.46,7142.44 h69
  text "0.4mil" at 7753.73,7142.44 h69
  text "Solder Resist" at 8525.66,7142.44 h69
  text "3.50" at 9509.72,7142.44 h69
  text "Top Layer L1" at 5018.02,6919.62 h69
  text "(.GTL)" at 6358.46,6919.62 h69
  text "0.6mil" at 7016.09,6919.62 h69
  text "4mil" at 7753.73,6808.21 h69
  text "Rogers RO4350" at 8525.66,6808.21 h69
  text "3.66" at 9509.72,6808.21 h69
  text "Core" at 10281.65,6808.21 h69
  text "Gnd-Plane - L2" at 5018.02,6696.8 h69
  text "(.GP1)" at 6358.46,6696.8 h69
  text "1.2mil" at 7016.09,6696.8 h69
  text "6.7mil" at 7753.73,6585.39 h69
  text "NP 4000-6" at 8525.66,6585.39 h69
  text "4.11" at 9509.72,6585.39 h69
  text "PrePreg" at 10281.65,6585.39 h69
  text "Signals - L3" at 5018.02,6473.98 h69
  text "(.G1)" at 6358.46,6473.98 h69
  text "0.6mil" at 7016.09,6473.98 h69
  text "6mil" at 7753.73,6362.57 h69
  text "NP 4000-6" at 8525.66,6362.57 h69
  text "4.11" at 9509.72,6362.57 h69
  text "Core" at 10281.65,6362.57 h69
  text "Gnd-Plane - L4" at 5018.02,6251.16 h69
  text "(.GP2)" at 6358.46,6251.16 h69
  text "1.2mil" at 7016.09,6251.16 h69
  text "4.1mil" at 7753.73,6139.75 h69
  text "NP 4000-6" at 8525.66,6139.75 h69
  text "4.11" at 9509.72,6139.75 h69
  text "PrePreg" at 10281.65,6139.75 h69
  text "SEE 001svengprerelstackup18.pdf FOR CORRECT STACKUP INFORMATION" at -46,6041 h66
  text "Pwr Plane - L5" at 5018.02,6028.34 h69
  text "(.GP3)" at 6358.46,6028.34 h69
  text "1.2mil" at 7016.09,6028.34 h69
  text "6mil" at 7753.73,5916.93 h69
  text "NP 4000-6" at 8525.66,5916.93 h69
  text "4.11" at 9509.72,5916.93 h69
  text "Core" at 10281.65,5916.93 h69
  text "Signals - L6" at 5018.02,5805.51 h69
  text "(.G2)" at 6358.46,5805.51 h69
  text "0.6mil" at 7016.09,5805.51 h69
  text "6.7mil" at 7753.73,5694.1 h69
  text "NP 4000-6" at 8525.66,5694.1 h69
  text "4.11" at 9509.72,5694.1 h69
  text "PrePreg" at 10281.65,5694.1 h69
  text "Gnd-Plane - L7" at 5018.02,5582.69 h69
  text "(.GP4)" at 6358.46,5582.69 h69
  text "1.2mil" at 7016.09,5582.69 h69
  text "4mil" at 7753.73,5471.28 h69
  text "Rogers RO4350" at 8525.66,5471.28 h69
  text "3.66" at 9509.72,5471.28 h69
  text "Core" at 10281.65,5471.28 h69
  text "Signals - L8" at 5018.02,5359.87 h69
  text "(.G3)" at 6358.46,5359.87 h69
  text "0.6mil" at 7016.09,5359.87 h69
  text "7.3mil" at 7753.73,5248.46 h69
  text "Rogers RO4350" at 8525.66,5248.46 h69
  text "3.66" at 9509.72,5248.46 h69
  text "PrePreg" at 10281.65,5248.46 h69
  text "Gnd-Plane - L9" at 5018.02,5137.05 h69
  text "(.GP5)" at 6358.46,5137.05 h69
  text "1.2mil" at 7016.09,5137.05 h69
  text "4mil" at 7753.73,5025.64 h69
  text "Rogers RO4350" at 8525.66,5025.64 h69
  text "3.66" at 9509.72,5025.64 h69
  text "Core" at 10281.65,5025.64 h69
  text "Bottom Layer - L10" at 5018.02,4914.23 h69
  text "(.GBL)" at 6358.46,4914.23 h69
  text "0.6mil" at 7016.09,4914.23 h69
  text "Bottom Solder Mask" at 5018.02,4691.41 h69
  text "(.GBS)" at 6358.46,4691.41 h69
  text "0.4mil" at 7753.73,4691.41 h69
  text "Solder Resist" at 8525.66,4691.41 h69
  text "3.50" at 9509.72,4691.41 h69
  text ".Layer_Name" at 577,-858.49 h60
M13 Component Bodies Top:
  text ".Layer_Name" at 577,-858.49 h60
M14 Component Bodies Bottom:
  text ".Layer_Name" at 577,-858.49 h60
M15 Courtyards Top:
  text ".Layer_Name" at 577,-858.49 h60
M16 Courtyards Bottom:
  text ".Layer_Name" at 577,-858.49 h60
Drill Drawing:
  text ".legend" at 5576.5,725.5 h60
  text "Drill Table" at 5601.5,540.5 h60
  text ".Layer_Name" at 577,-858.49 h60

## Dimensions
0,0 to 5404,0 on M2 Board Dimensions
0,0 to 0,2680 on M2 Board Dimensions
